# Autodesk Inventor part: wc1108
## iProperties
Shininess: 64.0
Length Units: 11272
Angle Units: 11279
Time Units: 11290
Mass Units: 11286
Length Display Precision: 3
Angle Display Precision: 2
Compacted: True
Part Number: wc1108
Document SubType Name: Modeling
Created: 2004-08
Designer: John Blackburn
Manufacturer: Standard
Standards Organization: Custom
Material: Phenolic
Density: 0.0
Volumn: 0.0
Area: 0.0
PropertySet Name: Model Information
Control State: 0
Master: False
Checked Out: False
Author: John Blackburn
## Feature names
1. Base1
